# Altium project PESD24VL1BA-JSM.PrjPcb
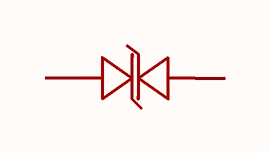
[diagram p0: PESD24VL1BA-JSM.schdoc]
1 sheet, 1 parts. Net scope: global (net labels, ports and power ports of the same name join across sheets).

## Sheet PESD24VL1BA-JSM.schdoc
size 127 x 101 mm

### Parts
D?  pesd24vl1ba-jsm  [SOD-323_L1.8-W1.3-LS2.5-BI]  (value not drawn)

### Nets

Not connected (* = marked no-connect by the designer): D? 1 2

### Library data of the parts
D? = pesd24vl1ba-jsm: 极性:双向;反向截止电压(Vrwm):24V;钳位电压:50V;峰值脉冲电流(Ipp):6A@8/20us;峰值脉冲功率(Ppp):300W@8/20us;击穿电压(VBR):26.7V;; Manufacturer: JSMSEMI(杰盛微); AddInBom: yes; ModelId: f9eb3c564310447fa7e5a2d35bef3787; ModelTransform: 98.425,51.181,0,0,0,0,0,0,0; Polarity: 双向; Reverse Stand-Off Voltage (Vrwm): 24V; Clamping Voltage: 50V; Voltage - Breakdown: 26.7V; Reverse Leakage Current (Ir): 500nA; Number of Channels: 单路; level of protection: IEC 61000-4-4；IEC 61000-4-5；IEC 61000-4-2; Type: ESD; Junction Capacitance: 15pF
